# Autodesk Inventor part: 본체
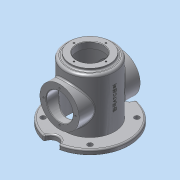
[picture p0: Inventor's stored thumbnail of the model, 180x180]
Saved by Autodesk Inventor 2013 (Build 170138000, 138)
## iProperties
Created: 2018-04
Part Number: 본체
Material: 알루미늄 6061
Document SubType Name: Modeling
Designer: dgall
Density: 2.71 g/cm^3
Mass: 1150.65 g
Surface Area: 1197.8 cm^2
Volume: 424.595 cm^3
Author: dgall
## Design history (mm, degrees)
sketch "스케치1"
  geometry: C1 r 50 at (0, 0); 2 further points
  constraints: 3 coincident, 1 centre point
  dimensions: "d19" = 100 diameter of C1
extrude "돌출1" new body sketch "스케치1" distance "d21" = 128; taper "d22" = 0 deg
sketch "스케치2"
  geometry: C1 r 50 at (0, 0) reference; C2 r 40 at (0, 0)
  constraints: 1 centre point, 1 coincident
  dimensions: "d23" = 80 diameter of C2
extrude "돌출2" join sketch "스케치2" distance "d24" = 5; taper "d25" = 0 deg
sketch "스케치3"
  geometry: C1 r 50 at (0, 0) reference; C2 r 45 at (0, 0)
  constraints: 1 centre point, 1 coincident
  dimensions: "d26" = 90 diameter of C2
extrude "돌출3" cut sketch "스케치3" distance "d27" = 120; taper "d28" = 0 deg
sketch "스케치4"
  geometry: C1 r 40 at (0, 0) reference; C2 r 27 at (0, 0)
  constraints: 1 centre point, 1 coincident
  dimensions: "d29" = 54 diameter of C2
extrude "돌출4" cut sketch "스케치4" distance "d30" = 120; taper "d31" = 0 deg
node "작업 평면1"
sketch "스케치5"
  geometry: L1 (0, 0)-(0, -80); L2 (0, 0)-(56.569, -56.569); C1 r 45 at (0, 0) reference; C2 r 50 at (0, 0) reference; A1 r 15 centre (0, -80) between (14.934, -78.594) and (-14.934, -78.594); A2 r 15 centre (0, 80) between (-14.934, 78.594) and (14.934, 78.594); A3 r 80 centre (0, 0) between (56.569, -56.569) and (14.934, 78.594); A4 r 80 centre (0, 0) between (-14.934, 78.594) and (-14.934, -78.594); A5 r 80 centre (0, 0) between (-78.594, -14.934) and (-14.934, -78.594); A6 r 80 centre (0, 0) between (14.934, -78.594) and (78.594, -14.934); 2 further points
  constraints: 13 point on circle, 6 centre point, 4 end point, 2 coincident, 2 vertical alignment, 1 concentric, 1 point on line, 1 vertical
  dimensions: "d34" = 45 deg angle of L2 L1; "d46" = 67.5 distance of point (0, 0) point (47.73, -47.73); "d101" = 30 diameter of A1; "d102" = 30 diameter of A2; "d103" = 80 distance of point (0, 0) A2.centre; "d104" = 80 radius of A4; "d105" = 80 radius of A3; "d106" = 80 distance of point (0, 0) A1.centre
  node "절단 모서리 투영1"
extrude "돌출5" join sketch "스케치5" distance "d44" = 10; taper "d45" = 0 deg
hole "구멍1" sketch "스케치5" diameter "d47" = 10; stored, may be unused: countersink angle "d51" = 90 deg, drill point angle "d53" = 118 deg; dims "d48" = 6, "d49" = 4, "d50" = 2, "d52" = 8
node "작업 평면2"
sketch "스케치6"
  geometry: L1 (-50.557, 8)-(-50.557, 18) reference; L2 (-50.557, 18)-(50.557, 18) reference; L3 (50.557, 8)-(-50.557, 8) reference; L4 (14.934, 8)-(-14.934, 8) reference; L5 (50.557, 18)-(50.557, 8) reference; C1 r 40 at (0, 68); C2 r 27 at (0, 68); 3 further points
  constraints: 2 centre point, 2 vertical alignment, 1 coincident
  dimensions: "d58" = 80 diameter of C1; "d59" = 54 diameter of C2; "d61" = 60 distance from line of L4 C1.centre; "d62" = 32.5 distance of C1.centre point (0, 100.5)
  node "절단 모서리 투영2"
extrude "돌출6" join sketch "스케치6" stored distance "d63" = 10; taper "d64" = 0 deg
extrude "돌출7" cut sketch "스케치6" stored distance "d65" = 10; taper "d66" = 0 deg
hole "구멍2" sketch "스케치6" diameter "d67" = 3.242; stored, may be unused: countersink angle "d71" = 90 deg, drill point angle "d73" = 118 deg; dims "d68" = 8, "d69" = 4, "d70" = 2, "d72" = 10
sketch "스케치7"
  geometry: C1 r 27 at (0, 0) reference; 1 further point
  constraints: 1 vertical alignment
  dimensions: "d77" = 32.5 distance of C1.centre point (0, 32.5)
hole "구멍3" sketch "스케치7" at (0, 32.5) diameter "d78" = 3.242; stored, may be unused: countersink angle "d82" = 90 deg, drill point angle "d84" = 118 deg; dims "d79" = 8, "d80" = 4, "d81" = 2, "d83" = 10
fillet "모깎기1" dims "d88" = 5
node "작업 평면3"
sketch "스케치8"
  geometry: 4 further points; 1 other entity
  constraints: 1 horizontal alignment, 1 vertical alignment, 1 other
  dimensions: "d90" = 70 dimension on point (0, 78)
feature "엠보싱1" sketch "스케치8" dims "d91" = 0.5, "d92" = 0
chamfer "모따기1" distance "d93" = 1; stored, may be unused: second distance "d94" = 2, angle "d95" = 45 deg
chamfer "모따기2" distance "d97" = 1; stored, may be unused: second distance "d98" = 2, angle "d99" = 45 deg
fillet "모깎기4" dims "d107" = 3
fillet "모깎기5" dims "d108" = 3
node "솔리드1"
pattern_circular "원형 패턴1" dims angle "d55" = 360 deg
pattern_circular "원형 패턴2" dims angle "d75" = 360 deg
mirror "대칭1"
pattern_circular "원형 패턴3" dims angle "d86" = 360 deg
other parameters: "d32" = -8, "d57" = 62
